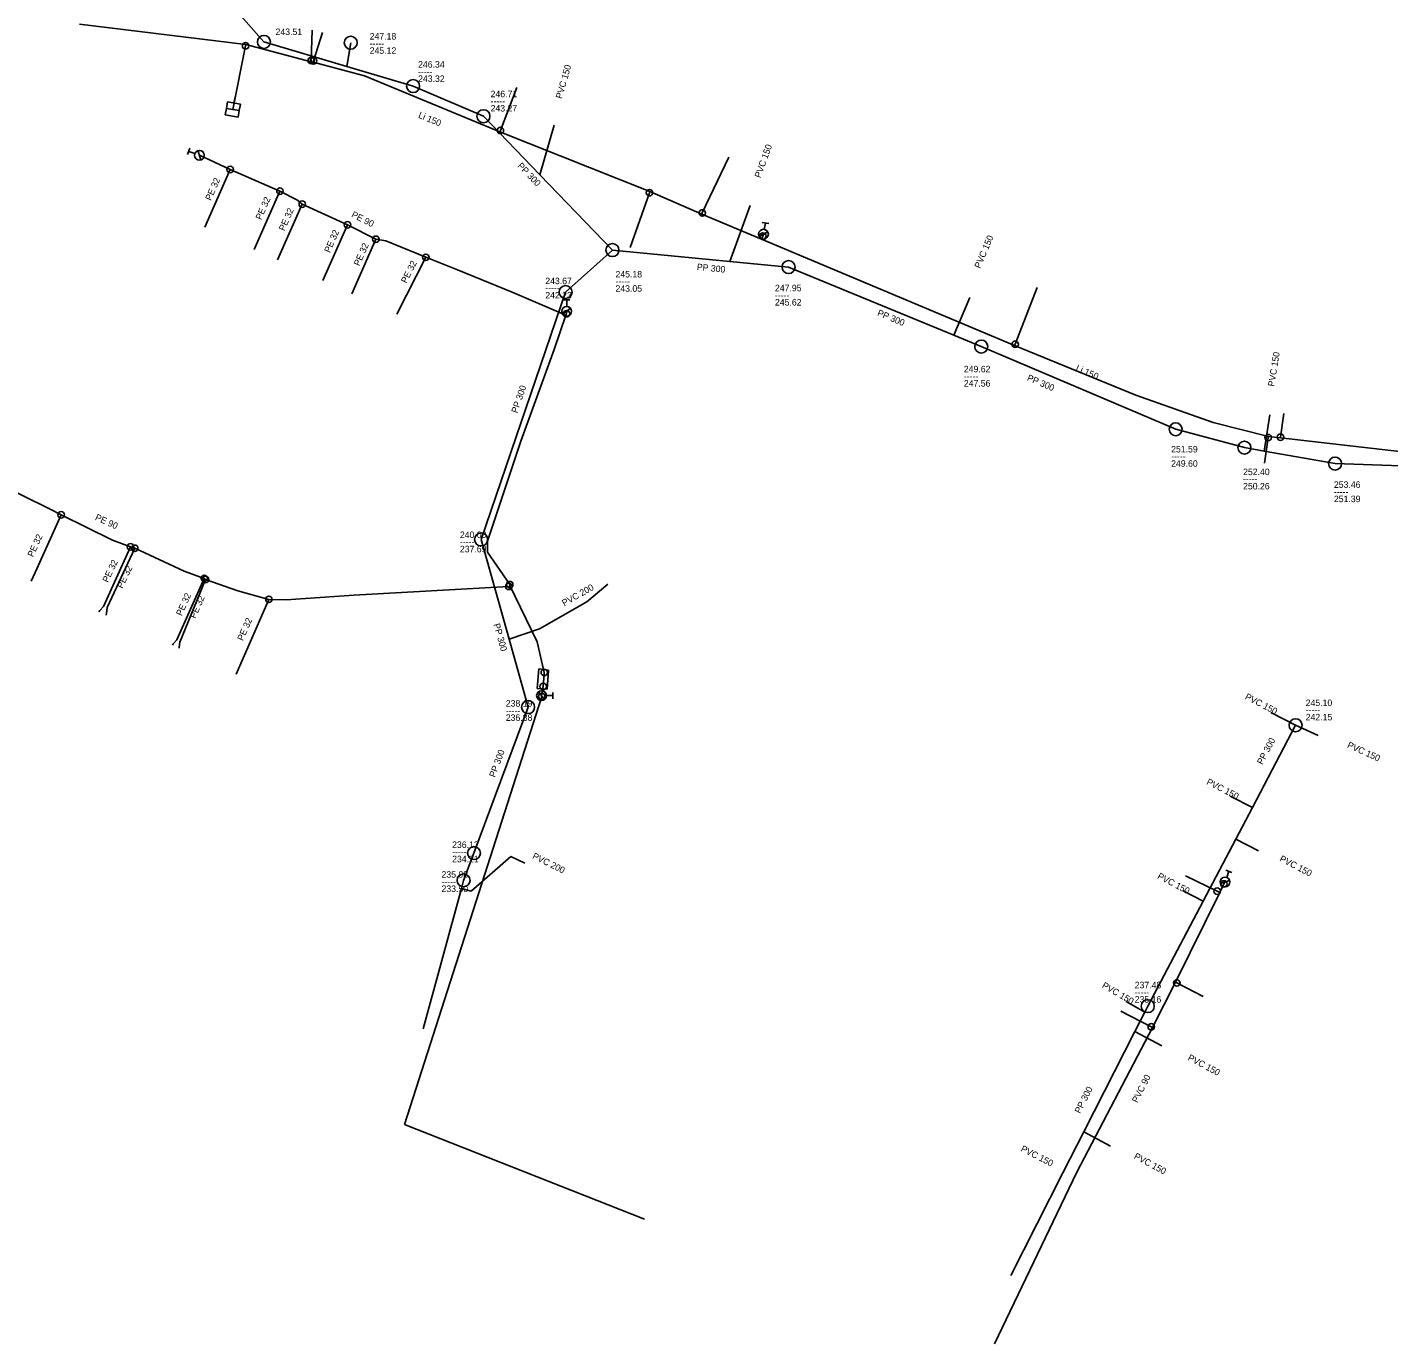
# Model space of a CAD drawing. Extents: x -771681 to -770485, y -1050143 to -1049574.
# Drawn here: x -771300.2 to -771090.5, y -1050074 to -1049871.3 of the extents above; entities that cross this region are included whole.
import ezdxf

# ---------------------------------------------------------------- set-up
doc = ezdxf.new("R2010")
doc.units = 0
doc.layers.add('Level 0', color=7, linetype='Continuous')

msp = doc.modelspace()

# ---------------------------------------------------------------- linework, layer by layer
at = {"layer": 'Level 0'}
for p, q in [((-771267.23, -1049869.61), (-771263.73, -1049873.6)), ((-771292.13, -1049870.85), (-771266.5, -1049873.98)), ((-771256.44, -1049876.45), (-771256.28, -1049871.77)), ((-771266.55, -1049874.21), (-771266.5, -1049873.98)), ((-771266.5, -1049873.98), (-771256.45, -1049876.65)), ((-771263.73, -1049873.6), (-771250.97, -1049877.37)), ((-771256.08, -1049876.52), (-771254.7, -1049872.15)), ((-771250.97, -1049877.37), (-771250.37, -1049873.72)), ((-771268.52, -1049884), (-771266.55, -1049874.21)), ((-771256.45, -1049876.65), (-771256.44, -1049876.45)), ((-771256.45, -1049876.65), (-771256.15, -1049876.73)), ((-771256.15, -1049876.73), (-771256.08, -1049876.52)), ((-771256.15, -1049876.73), (-771248.24, -1049878.82)), ((-771250.97, -1049877.37), (-771240.75, -1049880.39)), ((-771248.24, -1049878.82), (-771227.4, -1049887.44)), ((-771268.17, -1049882.03), (-771268.35, -1049883.02)), ((-771240.75, -1049880.39), (-771229.92, -1049885.03)), ((-771227.32, -1049887.24), (-771224.8, -1049880.64)), ((-771229.92, -1049885.03), (-771221.24, -1049894.08)), ((-771221.24, -1049894.08), (-771219.04, -1049886.41)), ((-771227.4, -1049887.44), (-771227.32, -1049887.24)), ((-771227.4, -1049887.44), (-771204.29, -1049896.63)), ((-771275.48, -1049890.92), (-771275.13, -1049889.98)), ((-771274.36, -1049890.79), (-771275.3, -1049890.45)), ((-771273.43, -1049891.76), (-771273.89, -1049890.34)), ((-771268.93, -1049893.25), (-771273.66, -1049891.05)), ((-771196.22, -1049899.93), (-771192.11, -1049891.35)), ((-771268.93, -1049893.25), (-771272.83, -1049902.11)), ((-771261.26, -1049896.57), (-771268.93, -1049893.25)), ((-771221.24, -1049894.08), (-771210.06, -1049905.65)), ((-771261.26, -1049896.57), (-771265.21, -1049905.54)), ((-771258.57, -1049897.96), (-771261.26, -1049896.57)), ((-771204.35, -1049896.81), (-771207.35, -1049905.27)), ((-771204.29, -1049896.63), (-771204.35, -1049896.81)), ((-771204.29, -1049896.63), (-771196.3, -1049900.1)), ((-771257.83, -1049898.57), (-771261.62, -1049907.17)), ((-771257.83, -1049898.57), (-771258.57, -1049897.96)), ((-771250.86, -1049901.75), (-771257.83, -1049898.57)), ((-771191.97, -1049907.39), (-771188.87, -1049898.8)), ((-771196.3, -1049900.1), (-771196.22, -1049899.93)), ((-771196.3, -1049900.1), (-771187.11, -1049903.96)), ((-771250.86, -1049901.75), (-771254.64, -1049910.34)), ((-771246.5, -1049903.98), (-771250.86, -1049901.75)), ((-771187.46, -1049903.55), (-771186.14, -1049902.85)), ((-771186.99, -1049901.39), (-771186, -1049901.56)), ((-771186.8, -1049903.2), (-771186.91, -1049903.48)), ((-771186.67, -1049902.46), (-771186.5, -1049901.48)), ((-771246.5, -1049903.98), (-771250.19, -1049912.37)), ((-771244.95, -1049904.21), (-771246.5, -1049903.98)), ((-771238.8, -1049906.76), (-771244.95, -1049904.21)), ((-771186.91, -1049903.48), (-771187.11, -1049903.96)), ((-771187.11, -1049903.96), (-771148.12, -1049920.32)), ((-771238.8, -1049906.76), (-771243.25, -1049915.53)), ((-771233.93, -1049908.69), (-771238.8, -1049906.76)), ((-771210.06, -1049905.65), (-771217.27, -1049912.1)), ((-771191.97, -1049907.39), (-771210.06, -1049905.65)), ((-771182.94, -1049908.26), (-771191.97, -1049907.39)), ((-771225.49, -1049912.12), (-771233.93, -1049908.69)), ((-771157.5, -1049918.75), (-771182.94, -1049908.26)), ((-771148.05, -1049920.15), (-771144.64, -1049911.42)), ((-771217.27, -1049912.1), (-771230.28, -1049950.19)), ((-771217.24, -1049915.66), (-771225.49, -1049912.12)), ((-771217.6, -1049913.32), (-771216.6, -1049913.32)), ((-771217.1, -1049914.32), (-771217.1, -1049913.32)), ((-771157.5, -1049918.75), (-771155.04, -1049912.95)), ((-771219.03, -1049920.96), (-771217.24, -1049915.66)), ((-771217.69, -1049915.53), (-771216.51, -1049914.61)), ((-771217.24, -1049915.66), (-771217.14, -1049915.44)), ((-771217.14, -1049915.44), (-771217.1, -1049915.07)), ((-771153.26, -1049920.5), (-771157.5, -1049918.75)), ((-771224.16, -1049935.06), (-771219.03, -1049920.96)), ((-771123.32, -1049933.23), (-771153.26, -1049920.5)), ((-771148.12, -1049920.32), (-771148.05, -1049920.15)), ((-771148.12, -1049920.32), (-771129.48, -1049928)), ((-771129.48, -1049928), (-771117.53, -1049932.18)), ((-771117.53, -1049932.18), (-771109.05, -1049934.34)), ((-771109.71, -1049936.59), (-771108.8, -1049930.99)), ((-771107.18, -1049934.46), (-771106.65, -1049930.81)), ((-771112.73, -1049936.06), (-771123.32, -1049933.23)), ((-771109.08, -1049934.52), (-771109.65, -1049938.45)), ((-771109.05, -1049934.34), (-771109.08, -1049934.52)), ((-771109.05, -1049934.34), (-771107.19, -1049934.56)), ((-771107.19, -1049934.56), (-771107.18, -1049934.46)), ((-771107.19, -1049934.56), (-771088.4, -1049936.68)), ((-771296.77, -1049945.49), (-771315.8, -1049936.07)), ((-771229.28, -1049950.45), (-771224.16, -1049935.06)), ((-771109.71, -1049936.59), (-771112.73, -1049936.06)), ((-771098.77, -1049938.52), (-771109.71, -1049936.59)), ((-771080.29, -1049939.18), (-771098.77, -1049938.52)), ((-771294.96, -1049946.41), (-771298.98, -1049955.26)), ((-771294.96, -1049946.41), (-771296.77, -1049945.49)), ((-771287.04, -1049950.31), (-771294.96, -1049946.41)), ((-771284.27, -1049951.34), (-771288.43, -1049960.51)), ((-771283.63, -1049951.55), (-771287.89, -1049960.69)), ((-771284.27, -1049951.34), (-771287.04, -1049950.31)), ((-771283.63, -1049951.55), (-771284.27, -1049951.34)), ((-771276.02, -1049955.05), (-771283.63, -1049951.55)), ((-771230.28, -1049950.19), (-771225.98, -1049965.52)), ((-771229.3, -1049952.13), (-771229.28, -1049950.45)), ((-771225.88, -1049957.14), (-771229.3, -1049952.13)), ((-771298.98, -1049955.26), (-771299.6, -1049956.63)), ((-771272.91, -1049956.18), (-771276.02, -1049955.05)), ((-771272.91, -1049956.18), (-771277.15, -1049965.62)), ((-771272.72, -1049956.36), (-771276.7, -1049966)), ((-771272.72, -1049956.36), (-771272.91, -1049956.18)), ((-771267.75, -1049958.09), (-771272.72, -1049956.36)), ((-771226.02, -1049957.42), (-771249.88, -1049958.75)), ((-771225.79, -1049957.38), (-771226.02, -1049957.42)), ((-771225.79, -1049957.38), (-771225.88, -1049957.14)), ((-771224.21, -1049960.65), (-771225.79, -1049957.38)), ((-771213.99, -1049959.8), (-771210.76, -1049957.09)), ((-771262.96, -1049959.41), (-771268.02, -1049970.92)), ((-771262.96, -1049959.41), (-771267.75, -1049958.09)), ((-771260.3, -1049959.49), (-771262.96, -1049959.41)), ((-771249.88, -1049958.75), (-771260.3, -1049959.49)), ((-771221.31, -1049963.93), (-771213.99, -1049959.8)), ((-771289.01, -1049961.14), (-771289.18, -1049961.33)), ((-771288.43, -1049960.51), (-771289.01, -1049961.14)), ((-771287.98, -1049961.59), (-771288.01, -1049961.86)), ((-771287.89, -1049960.69), (-771287.98, -1049961.59)), ((-771221.63, -1049965.97), (-771224.21, -1049960.65)), ((-771225.98, -1049965.52), (-771221.31, -1049963.93)), ((-771277.15, -1049965.62), (-771277.69, -1049966.28)), ((-771276.7, -1049966), (-771276.76, -1049966.75)), ((-771225.98, -1049965.52), (-771223.04, -1049976)), ((-771220.55, -1049970.67), (-771221.63, -1049965.97)), ((-771277.69, -1049966.28), (-771277.83, -1049966.46)), ((-771276.76, -1049966.75), (-771276.78, -1049966.93)), ((-771221.37, -1049970.13), (-771221.65, -1049973.12)), ((-771219.92, -1049970.34), (-771221.37, -1049970.13)), ((-771220.13, -1049973.26), (-771219.92, -1049970.34)), ((-771220.74, -1049972.82), (-771220.65, -1049971.56)), ((-771220.65, -1049971.56), (-771220.55, -1049971.09)), ((-771220.55, -1049971.09), (-771220.55, -1049970.67)), ((-771220.95, -1049974.35), (-771242.06, -1050040.24)), ((-771221.65, -1049973.12), (-771220.13, -1049973.26)), ((-771221.44, -1049973.64), (-771220.52, -1049974.82)), ((-771220.98, -1049974.23), (-771220.74, -1049972.82)), ((-771220.98, -1049974.23), (-771220.95, -1049974.35)), ((-771220.23, -1049974.23), (-771219.23, -1049974.23)), ((-771219.23, -1049973.73), (-771219.23, -1049974.73)), ((-771223.04, -1049976), (-771231.38, -1049998.48)), ((-771104.85, -1049978.79), (-771111.51, -1049991.45)), ((-771104.85, -1049978.79), (-771108.65, -1049976.81)), ((-771104.85, -1049978.79), (-771101.39, -1049980.36)), ((-771111.51, -1049991.45), (-771114.91, -1049989.71)), ((-771111.51, -1049991.45), (-771114.07, -1049996.31)), ((-771114.07, -1049996.31), (-771119.11, -1050005.9)), ((-771114.07, -1049996.31), (-771110.56, -1049998.14)), ((-771231.38, -1049998.48), (-771232.99, -1050002.67)), ((-771231.83, -1050004.36), (-771225.73, -1049999)), ((-771225.73, -1049999), (-771223.55, -1050000.04)), ((-771115.59, -1050001.09), (-771114.65, -1050001.44)), ((-771115.46, -1050002.21), (-771115.12, -1050001.27)), ((-771233.33, -1050003.92), (-771239.22, -1050025.54)), ((-771232.99, -1050002.67), (-771233.33, -1050003.92)), ((-771233.33, -1050003.92), (-771231.83, -1050004.36)), ((-771116.92, -1050004.34), (-771121.81, -1050001.97)), ((-771116.54, -1050004.53), (-771115.9, -1050003.22)), ((-771116.43, -1050003.14), (-771115.01, -1050002.68)), ((-771115.9, -1050003.22), (-771115.72, -1050002.91)), ((-771119.11, -1050005.9), (-771127.61, -1050022.04)), ((-771123.35, -1050018.33), (-771116.54, -1050004.53)), ((-771119.11, -1050005.9), (-771122.18, -1050004.28)), ((-771116.54, -1050004.53), (-771116.92, -1050004.34)), ((-771126.9, -1050025.32), (-771123.35, -1050018.33)), ((-771123.35, -1050018.33), (-771123.15, -1050018.47)), ((-771123.15, -1050018.47), (-771119.1, -1050020.57)), ((-771127.08, -1050025.23), (-771131.79, -1050022.83)), ((-771128.08, -1050022.96), (-771130.92, -1050021.31)), ((-771127.61, -1050022.04), (-771128.08, -1050022.96)), ((-771128.08, -1050022.96), (-771129.59, -1050025.93)), ((-771138.55, -1050047.57), (-771126.9, -1050025.32)), ((-771129.59, -1050025.93), (-771137.46, -1050041.37)), ((-771129.59, -1050025.93), (-771125.43, -1050028.15)), ((-771126.9, -1050025.32), (-771127.08, -1050025.23)), ((-771242.06, -1050040.24), (-771205.12, -1050054.85)), ((-771137.46, -1050041.37), (-771140.68, -1050047.69)), ((-771137.46, -1050041.37), (-771133.36, -1050043.59)), ((-771151.23, -1050074.01), (-771138.55, -1050047.57)), ((-771140.68, -1050047.69), (-771148.73, -1050063.48))]:
    msp.add_line(p, q, dxfattribs=at)
msp.add_lwpolyline([(-771267.54, -1049884.17), (-771267.71, -1049885.16), (-771269.68, -1049884.81), (-771269.5, -1049883.83)], dxfattribs=at)
msp.add_lwpolyline([(-771267.36, -1049883.19), (-771269.33, -1049882.84), (-771269.5, -1049883.83), (-771267.54, -1049884.17)], close=True, dxfattribs=at)
for centre, radius in [((-771266.55, -1049874.21), 0.5), ((-771263.73, -1049873.6), 1), ((-771250.37, -1049873.72), 1), ((-771256.44, -1049876.45), 0.5), ((-771256.08, -1049876.52), 0.5), ((-771240.75, -1049880.39), 1), ((-771229.92, -1049885.03), 1), ((-771227.32, -1049887.24), 0.5), ((-771273.66, -1049891.05), 0.75), ((-771268.93, -1049893.25), 0.5), ((-771261.26, -1049896.57), 0.5), ((-771204.35, -1049896.81), 0.5), ((-771257.83, -1049898.57), 0.5), ((-771250.86, -1049901.75), 0.5), ((-771196.22, -1049899.93), 0.5), ((-771186.8, -1049903.2), 0.75), ((-771186.91, -1049903.48), 0.5), ((-771246.5, -1049903.98), 0.5), ((-771210.06, -1049905.65), 1), ((-771238.8, -1049906.76), 0.5), ((-771182.94, -1049908.26), 1), ((-771217.27, -1049912.1), 1), ((-771217.1, -1049915.07), 0.75), ((-771217.14, -1049915.44), 0.5), ((-771153.26, -1049920.5), 1), ((-771148.05, -1049920.15), 0.5), ((-771123.32, -1049933.23), 1), ((-771109.08, -1049934.52), 0.5), ((-771107.18, -1049934.46), 0.5), ((-771112.73, -1049936.06), 1), ((-771098.77, -1049938.52), 1), ((-771294.96, -1049946.41), 0.5), ((-771230.28, -1049950.19), 1), ((-771284.27, -1049951.34), 0.5), ((-771283.63, -1049951.55), 0.5), ((-771272.91, -1049956.18), 0.5), ((-771272.72, -1049956.36), 0.5), ((-771226.02, -1049957.42), 0.5), ((-771225.88, -1049957.14), 0.5), ((-771262.96, -1049959.41), 0.5), ((-771220.55, -1049970.67), 0.5), ((-771220.74, -1049972.82), 0.5), ((-771220.98, -1049974.23), 0.75), ((-771220.95, -1049974.35), 0.5), ((-771223.04, -1049976), 1), ((-771104.85, -1049978.79), 1), ((-771231.38, -1049998.48), 1), ((-771232.99, -1050002.67), 1), ((-771116.92, -1050004.34), 0.5), ((-771115.72, -1050002.91), 0.75), ((-771115.9, -1050003.22), 0.5), ((-771123.15, -1050018.47), 0.5), ((-771127.61, -1050022.04), 1), ((-771127.08, -1050025.23), 0.5)]:
    msp.add_circle(centre, radius, dxfattribs=at)

# ---------------------------------------------------------------- texts
for s, p in [('243.51', (-771261.94, -1049872.54)), ('-----', (-771247.44, -1049874.33)), ('247.18', (-771247.44, -1049873.23)), ('245.12', (-771247.44, -1049875.43)), ('246.34', (-771239.99, -1049877.56)), ('-----', (-771239.99, -1049878.66)), ('243.32', (-771239.99, -1049879.76)), ('246.71', (-771228.82, -1049882.11)), ('-----', (-771228.82, -1049883.21)), ('243.27', (-771228.82, -1049884.31)), ('245.18', (-771209.59, -1049909.86)), ('-----', (-771220.4, -1049911.99)), ('243.67', (-771220.4, -1049910.89)), ('-----', (-771209.59, -1049910.96)), ('243.05', (-771209.59, -1049912.06)), ('247.95', (-771185.03, -1049911.98)), ('242.23', (-771220.4, -1049913.09)), ('-----', (-771185.03, -1049913.08)), ('245.62', (-771185.03, -1049914.18)), ('249.62', (-771155.94, -1049924.46)), ('-----', (-771155.94, -1049925.56)), ('247.56', (-771155.94, -1049926.66)), ('251.59', (-771124.02, -1049936.8)), ('-----', (-771124.02, -1049937.9)), ('249.60', (-771124.02, -1049939)), ('-----', (-771112.94, -1049941.39)), ('252.40', (-771112.94, -1049940.29)), ('250.26', (-771112.94, -1049942.49)), ('-----', (-771098.95, -1049943.35)), ('253.46', (-771098.95, -1049942.25)), ('251.39', (-771098.95, -1049944.45)), ('240.00', (-771233.55, -1049949.97)), ('-----', (-771233.55, -1049951.07)), ('237.69', (-771233.55, -1049952.17)), ('-----', (-771226.48, -1049977.02)), ('238.19', (-771226.48, -1049975.92)), ('-----', (-771103.3, -1049976.94)), ('245.10', (-771103.3, -1049975.84)), ('236.88', (-771226.48, -1049978.12)), ('242.15', (-771103.3, -1049978.04)), ('236.12', (-771234.75, -1049997.68)), ('-----', (-771234.75, -1049998.78)), ('234.21', (-771234.75, -1049999.88)), ('235.98', (-771236.38, -1050002.26)), ('-----', (-771236.38, -1050003.36)), ('233.50', (-771236.38, -1050004.46)), ('237.48', (-771129.63, -1050019.29)), ('-----', (-771129.63, -1050020.39)), ('235.16', (-771129.63, -1050021.49))]:
    msp.add_text(s, height=1, dxfattribs=at).set_placement(p)
for s, rotation, p in [('PVC 150', 73.995, (-771217.86, -1049882.42)), ('Li 150', 337.529, (-771240.05, -1049885.23)), ('PVC 150', 70.156, (-771187.27, -1049894.62)), ('PP 300', 313.804, (-771224.76, -1049892.76)), ('PE 32', 66.242, (-771271.9, -1049898.11)), ('PE 32', 66.233, (-771264.15, -1049901.07)), ('PE 32', 66.217, (-771260.57, -1049902.78)), ('PE 90', 332.912, (-771250.35, -1049900.49)), ('PE 32', 66.248, (-771253.58, -1049906.14)), ('PE 32', 66.26, (-771249.03, -1049908.17)), ('PVC 150', 67.016, (-771153.44, -1049908.55)), ('PE 32', 63.096, (-771241.79, -1049910.84)), ('PP 300', 354.497, (-771197.09, -1049908.71)), ('PP 300', 337.572, (-771169.36, -1049915.69)), ('PVC 150', 80.77, (-771108.14, -1049926.7)), ('Li 150', 336.251, (-771138.8, -1049924.16)), ('PP 300', 336.966, (-771146.3, -1049925.67)), ('PP 300', 71.142, (-771224.72, -1049930.82)), ('PE 90', 335.301, (-771289.82, -1049947.13)), ('PE 32', 65.651, (-771299.28, -1049952.98)), ('PE 32', 64.485, (-771287.76, -1049956.9)), ('PE 32', 64.522, (-771285.52, -1049957.81)), ('PVC 200', 29.432, (-771217.48, -1049960.49)), ('PE 32', 65.721, (-771276.4, -1049962.04)), ('PE 32', 66.395, (-771274.28, -1049962.44)), ('PE 32', 66.269, (-771266.96, -1049965.88)), ('PP 300', 285.669, (-771228.39, -1049963.27)), ('PVC 150', 332.478, (-771112.74, -1049974.71)), ('PP 300', 62.222, (-771109.97, -1049984.94)), ('PP 300', 69.645, (-771228.15, -1049986.89)), ('PVC 150', 335.593, (-771096.99, -1049982.19)), ('PVC 150', 332.898, (-771118.68, -1049987.83)), ('PVC 200', 333.325, (-771222.48, -1049999.25)), ('PVC 150', 332.464, (-771107.41, -1049999.65)), ('PVC 150', 332.18, (-771126.23, -1050002.33)), ('PVC 150', 329.844, (-771134.76, -1050019.13)), ('PVC 150', 331.913, (-771121.55, -1050030.28)), ('PVC 90', 63.075, (-771129.22, -1050037)), ('PP 300', 62.991, (-771138.05, -1050038.64)), ('PVC 150', 332.815, (-771147.26, -1050044.31)), ('PVC 150', 331.566, (-771129.84, -1050045.44))]:
    msp.add_text(s, height=1, rotation=rotation, dxfattribs=at).set_placement(p)

doc.saveas('drawing.dxf')
